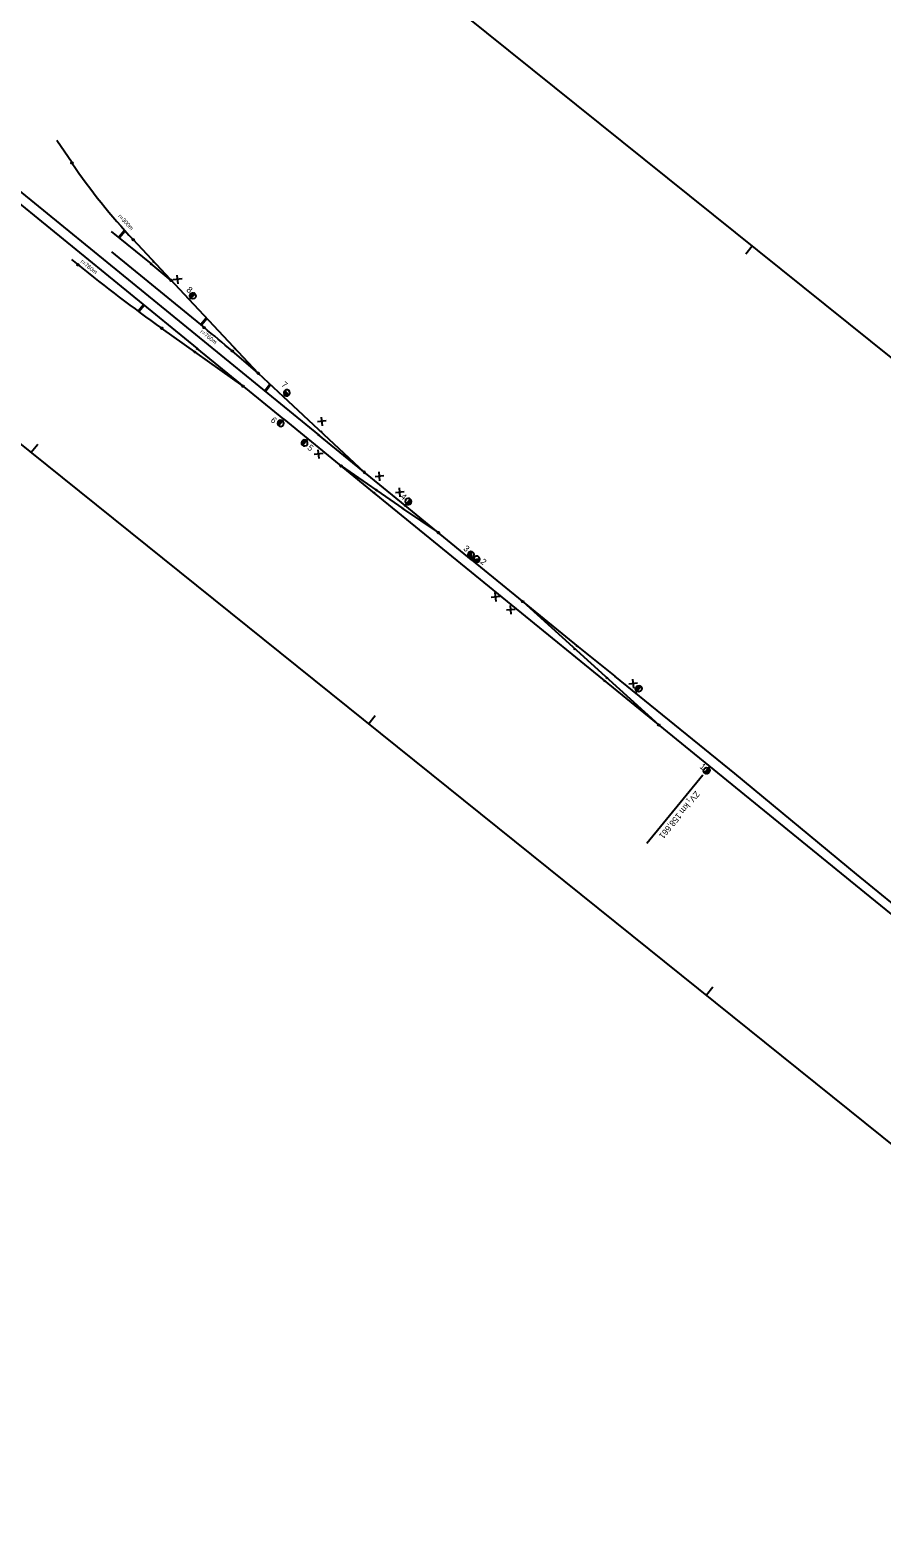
# Model space of a CAD drawing. Extents: x -486838 to -485015, y -1312876 to -1311330.
# Drawn here: x -485856 to -485443, y -1312876 to -1312145 of the extents above; entities that cross this region are included whole.
import ezdxf

# ---------------------------------------------------------------- set-up
doc = ezdxf.new("R2010")
doc.units = 0
for name, color, linetype in [('kolaj s', 7, 'Continuous'), ('Level 61', 7, 'Continuous'), ('popis 25', 7, 'Continuous'), ('popis 35', 7, 'Continuous')]:
    doc.layers.add(name, color=color, linetype=linetype)

msp = doc.modelspace()

# ---------------------------------------------------------------- linework, layer by layer
at = {"layer": 'kolaj s'}
for p, q in [((-485943.07, -1312156.89), (-485716.4, -1312341.55)), ((-485946.04, -1312160.6), (-485775.23, -1312299.76)), ((-485835.95, -1312209.75), (-485843.28, -1312198.9)), ((-485835.95, -1312209.75), (-485835.95, -1312209.75)), ((-485816.91, -1312242.92), (-485797.53, -1312258.7)), ((-485816.84, -1312252.88), (-485771.86, -1312289.52)), ((-485779.14, -1312275.89), (-485806.3, -1312246.91)), ((-485806.3, -1312246.91), (-485806.3, -1312246.91)), ((-485836.15, -1312256.51), (-485833.02, -1312259.06)), ((-485833.02, -1312259.06), (-485833.02, -1312259.06)), ((-485797.85, -1312259.09), (-485797.21, -1312258.32)), ((-485787.77, -1312266.69), (-485797.53, -1312258.7)), ((-485797.53, -1312258.7), (-485797.53, -1312258.7)), ((-485796.76, -1312257.82), (-485796.03, -1312257.14)), ((-485796.39, -1312257.48), (-485796.39, -1312257.48)), ((-485787.77, -1312266.69), (-485787.77, -1312266.69)), ((-485745.61, -1312311.68), (-485779.14, -1312275.89)), ((-485752.94, -1312317.91), (-485792.5, -1312289.87)), ((-485792.5, -1312289.87), (-485792.5, -1312289.87)), ((-485771.86, -1312289.52), (-485771.86, -1312289.52)), ((-485776.68, -1312301.7), (-485776.1, -1312300.88)), ((-485776.39, -1312301.29), (-485776.39, -1312301.29)), ((-485775.54, -1312300.14), (-485774.91, -1312299.37)), ((-485733.19, -1312334), (-485775.23, -1312299.76)), ((-485775.23, -1312299.76), (-485775.23, -1312299.76)), ((-485758.56, -1312301.27), (-485757.91, -1312300.51)), ((-485745.6, -1312311.68), (-485758.23, -1312300.89)), ((-485758.23, -1312300.89), (-485758.23, -1312300.89)), ((-485758.23, -1312300.89), (-485758.23, -1312300.89)), ((-485757.33, -1312299.9), (-485756.6, -1312299.22)), ((-485756.97, -1312299.56), (-485756.97, -1312299.56)), ((-485745.61, -1312311.68), (-485733.45, -1312323.02)), ((-485745.6, -1312311.68), (-485745.6, -1312311.68)), ((-485752.94, -1312317.91), (-485752.94, -1312317.91)), ((-485694.12, -1312359.71), (-485733.45, -1312323.02)), ((-485733.19, -1312334), (-485721.57, -1312343.47)), ((-485716.09, -1312341.16), (-485716.72, -1312341.94)), ((-485674.37, -1312375.79), (-485716.4, -1312341.55)), ((-485716.4, -1312341.55), (-485716.4, -1312341.55)), ((-485714.8, -1312339.73), (-485715.48, -1312340.47)), ((-485715.14, -1312340.1), (-485715.14, -1312340.1)), ((-485721.57, -1312343.47), (-485689.32, -1312369.74)), ((-485705.44, -1312356.61), (-485705.44, -1312356.61)), ((-485705.44, -1312356.61), (-485675.41, -1312377.18)), ((-485694.12, -1312359.71), (-485694.12, -1312359.71)), ((-485689, -1312369.36), (-485689.63, -1312370.13)), ((-485689.32, -1312369.74), (-485507.15, -1312518.16)), ((-485689.32, -1312369.74), (-485689.32, -1312369.74)), ((-485688, -1312367.95), (-485688.57, -1312368.77)), ((-485688.28, -1312368.36), (-485688.28, -1312368.36)), ((-485675.69, -1312377.59), (-485675.13, -1312376.77)), ((-485658.25, -1312388.93), (-485675.41, -1312377.18)), ((-485675.41, -1312377.18), (-485675.41, -1312377.18)), ((-485674.69, -1312376.18), (-485674.06, -1312375.41)), ((-485642.13, -1312402.07), (-485674.37, -1312375.79)), ((-485674.37, -1312375.79), (-485674.37, -1312375.79)), ((-485658.25, -1312388.93), (-485658.25, -1312388.93)), ((-485642.13, -1312402.07), (-485590.38, -1312444.22)), ((-485617.3, -1312422.29), (-485617.3, -1312422.29)), ((-485617.3, -1312422.29), (-485551.36, -1312482.14)), ((-485591.3, -1312444.11), (-485590.67, -1312443.33)), ((-485590.99, -1312443.72), (-485590.99, -1312443.72)), ((-485592.45, -1312445.55), (-485591.83, -1312444.77)), ((-485592.14, -1312445.16), (-485592.14, -1312445.16)), ((-485590.38, -1312444.22), (-485572.58, -1312458.46)), ((-485514.47, -1312505.69), (-485572.58, -1312458.46)), ((-485578, -1312461.04), (-485577.37, -1312460.26)), ((-485577.69, -1312460.65), (-485577.69, -1312460.65)), ((-485576.88, -1312459.65), (-485576.25, -1312458.87)), ((-485576.57, -1312459.26), (-485576.57, -1312459.26)), ((-485562.68, -1312466.58), (-485560.2, -1312463.51)), ((-485562.68, -1312466.58), (-485562.68, -1312466.58)), ((-485551.36, -1312482.14), (-485551.36, -1312482.14)), ((-485455.34, -1312554.41), (-485514.47, -1312505.69)), ((-485507.15, -1312518.16), (-485448.93, -1312565.48)), ((-485381.66, -1312614.83), (-485455.34, -1312554.41)), ((-485448.93, -1312565.48), (-485366.11, -1312632.98))]:
    msp.add_line(p, q, dxfattribs=at)
for points in [[(-485835.62, -1312209.53), (-485835.6, -1312209.92), (-485835.92, -1312210.15), (-485836.28, -1312209.97), (-485836.31, -1312209.57), (-485835.98, -1312209.35), (-485835.62, -1312209.53)], [(-485806.59, -1312247.18), (-485806.68, -1312246.79), (-485806.39, -1312246.52), (-485806.01, -1312246.63), (-485805.92, -1312247.02), (-485806.21, -1312247.3), (-485806.59, -1312247.18)], [(-485832.77, -1312258.75), (-485832.63, -1312259.12), (-485832.88, -1312259.43), (-485833.27, -1312259.37), (-485833.41, -1312258.99), (-485833.16, -1312258.69), (-485832.77, -1312258.75)], [(-485787.51, -1312266.38), (-485787.37, -1312266.75), (-485787.63, -1312267.06), (-485788.02, -1312267), (-485788.16, -1312266.62), (-485787.91, -1312266.31), (-485787.51, -1312266.38)], [(-485792.73, -1312290.2), (-485792.89, -1312289.84), (-485792.66, -1312289.51), (-485792.27, -1312289.55), (-485792.1, -1312289.91), (-485792.33, -1312290.24), (-485792.73, -1312290.2)], [(-485771.61, -1312289.21), (-485771.47, -1312289.58), (-485771.72, -1312289.89), (-485772.12, -1312289.83), (-485772.26, -1312289.45), (-485772.01, -1312289.15), (-485771.61, -1312289.21)], [(-485758.49, -1312301.19), (-485758.63, -1312300.82), (-485758.37, -1312300.51), (-485757.97, -1312300.58), (-485757.84, -1312300.96), (-485758.1, -1312301.27), (-485758.49, -1312301.19)], [(-485745.9, -1312311.41), (-485745.52, -1312311.3), (-485745.22, -1312311.57), (-485745.31, -1312311.96), (-485745.7, -1312312.07), (-485745.99, -1312311.8), (-485745.9, -1312311.41)], [(-485752.71, -1312317.58), (-485752.54, -1312317.95), (-485752.78, -1312318.27), (-485753.17, -1312318.24), (-485753.34, -1312317.87), (-485753.11, -1312317.55), (-485752.71, -1312317.58)], [(-485705.13, -1312356.86), (-485705.51, -1312357), (-485705.81, -1312356.75), (-485705.75, -1312356.36), (-485705.38, -1312356.22), (-485705.07, -1312356.47), (-485705.13, -1312356.86)], [(-485694.39, -1312360), (-485694, -1312360.09), (-485693.73, -1312359.8), (-485693.85, -1312359.41), (-485694.24, -1312359.33), (-485694.51, -1312359.62), (-485694.39, -1312360)], [(-485658.56, -1312388.68), (-485658.19, -1312388.54), (-485657.88, -1312388.79), (-485657.94, -1312389.18), (-485658.32, -1312389.32), (-485658.62, -1312389.07), (-485658.56, -1312388.68)], [(-485617.05, -1312421.98), (-485616.9, -1312422.35), (-485617.15, -1312422.66), (-485617.55, -1312422.6), (-485617.69, -1312422.23), (-485617.44, -1312421.92), (-485617.05, -1312421.98)], [(-485560.51, -1312463.26), (-485559.88, -1312463.76), (-485559.62, -1312464.51), (-485559.74, -1312465.25), (-485560.23, -1312465.85), (-485560.95, -1312466.13), (-485561.71, -1312466.01), (-485562.33, -1312465.51), (-485562.6, -1312464.79), (-485562.48, -1312464.03), (-485561.98, -1312463.41), (-485561.26, -1312463.14), (-485560.51, -1312463.26), (-485560.86, -1312463.29), (-485560.47, -1312463.61), (-485560.66, -1312463.84), (-485561.32, -1312463.3), (-485561.66, -1312463.41), (-485560.85, -1312464.07), (-485561.04, -1312464.31), (-485561.93, -1312463.58), (-485562.12, -1312463.81), (-485561.23, -1312464.54), (-485561.41, -1312464.78), (-485562.3, -1312464.05), (-485562.38, -1312464.37), (-485561.6, -1312465.01), (-485561.79, -1312465.24), (-485562.45, -1312464.7), (-485562.37, -1312465.16), (-485561.98, -1312465.47)], [(-485551.11, -1312481.83), (-485550.97, -1312482.2), (-485551.21, -1312482.51), (-485551.61, -1312482.45), (-485551.75, -1312482.07), (-485551.5, -1312481.76), (-485551.11, -1312481.83)]]:
    msp.add_lwpolyline(points, dxfattribs=at)
for centre, radius, start, end in [((-485587.38, -1312041.78), 300, 214.04753, 223.13629), ((-485353.01, -1311669.83), 760, 230.83205, 234.67055), ((-486251.86, -1312878.76), 760, 49.49538, 50.83347)]:
    msp.add_arc(centre, radius, start, end, dxfattribs=at)
at = {"layer": 'Level 61'}
for p, q in [((-486160.87, -1311724.08), (-485014.82, -1312644.65)), ((-485200.81, -1312876.2), (-486346.87, -1311955.63)), ((-485505.98, -1312250.12), (-485509.11, -1312254.02)), ((-485852.57, -1312346.26), (-485855.7, -1312350.16)), ((-485688.85, -1312477.77), (-485691.98, -1312481.67)), ((-485525.12, -1312609.28), (-485528.25, -1312613.18))]:
    msp.add_line(p, q, dxfattribs=at)
at = {"layer": 'popis 25'}
for p, q in [((-485813.02, -1312245.41), (-485810.84, -1312242.67)), ((-485812.67, -1312245.69), (-485810.49, -1312242.96)), ((-485803.69, -1312281.23), (-485801.51, -1312278.49)), ((-485803.33, -1312281.51), (-485801.15, -1312278.78)), ((-485773.27, -1312287.78), (-485771.09, -1312285.04)), ((-485772.91, -1312288.06), (-485770.73, -1312285.32)), ((-485742.3, -1312319.92), (-485740.12, -1312317.18)), ((-485741.95, -1312320.2), (-485739.76, -1312317.47))]:
    msp.add_line(p, q, dxfattribs=at)
at = {"layer": 'popis 35'}
for p, q in [((-485782.57, -1312265.97), (-485786.82, -1312266.44)), ((-485784.47, -1312268.33), (-485784.93, -1312264.08)), ((-485779.14, -1312275.89), (-485776.27, -1312273.18)), ((-485779.14, -1312275.89), (-485779.14, -1312275.89)), ((-485732.77, -1312322.28), (-485733.45, -1312323.02)), ((-485732.84, -1312320.16), (-485733.22, -1312320.84)), ((-485733.22, -1312320.84), (-485733.2, -1312321.57)), ((-485732.77, -1312322.28), (-485733.21, -1312321.58)), ((-485733.2, -1312321.57), (-485732.77, -1312322.28)), ((-485732.55, -1312320.73), (-485733.02, -1312321.23)), ((-485733.02, -1312321.23), (-485732.93, -1312321.58)), ((-485732.93, -1312321.58), (-485732.22, -1312320.81)), ((-485732.22, -1312319.75), (-485732.84, -1312320.16)), ((-485731.93, -1312320.95), (-485732.78, -1312321.86)), ((-485732.78, -1312321.86), (-485732.77, -1312322.28)), ((-485732.77, -1312322.28), (-485731.69, -1312321.13)), ((-485732.77, -1312322.28), (-485731.69, -1312321.13)), ((-485732.35, -1312322.27), (-485732.77, -1312322.28)), ((-485732.77, -1312322.28), (-485732.04, -1312322.67)), ((-485731.49, -1312321.35), (-485732.35, -1312322.27)), ((-485731.47, -1312319.7), (-485732.22, -1312319.75)), ((-485732.06, -1312322.4), (-485731.34, -1312321.63)), ((-485731.7, -1312322.46), (-485732.06, -1312322.4)), ((-485732.04, -1312322.67), (-485731.32, -1312322.61)), ((-485731.24, -1312321.96), (-485731.7, -1312322.46)), ((-485730.72, -1312320.09), (-485731.47, -1312319.7)), ((-485731.32, -1312322.61), (-485730.65, -1312322.21)), ((-485730.3, -1312320.81), (-485730.72, -1312320.09)), ((-485730.65, -1312322.21), (-485730.32, -1312321.56)), ((-485730.32, -1312321.56), (-485730.3, -1312320.81)), ((-485733.19, -1312334), (-485735.67, -1312337.08)), ((-485733.19, -1312334), (-485733.19, -1312334)), ((-485714.52, -1312337.15), (-485714.99, -1312332.9)), ((-485712.63, -1312334.79), (-485716.88, -1312335.26)), ((-485721.57, -1312343.47), (-485724.04, -1312346.55)), ((-485721.57, -1312343.47), (-485721.57, -1312343.47)), ((-485716.08, -1312353), (-485716.54, -1312348.75)), ((-485714.18, -1312350.65), (-485718.43, -1312351.11)), ((-485684.67, -1312361.42), (-485688.92, -1312361.88)), ((-485686.56, -1312363.77), (-485687.03, -1312359.52)), ((-485674.81, -1312369.19), (-485679.06, -1312369.65)), ((-485676.71, -1312371.54), (-485677.17, -1312367.29)), ((-485674.37, -1312375.79), (-485671.9, -1312372.72)), ((-485674.37, -1312375.79), (-485674.37, -1312375.79)), ((-485642.13, -1312402.07), (-485642.13, -1312402.07)), ((-485628.34, -1312419.9), (-485632.59, -1312420.36)), ((-485630.23, -1312422.26), (-485630.7, -1312418.01)), ((-485620.96, -1312426.12), (-485625.21, -1312426.59)), ((-485622.86, -1312428.48), (-485623.32, -1312424.23)), ((-485561.61, -1312461.91), (-485565.86, -1312462.37)), ((-485563.5, -1312464.26), (-485563.96, -1312460.01)), ((-485526.53, -1312502.37), (-485529, -1312505.45)), ((-485526.53, -1312502.37), (-485526.53, -1312502.37)), ((-485529.92, -1312506.5), (-485557.1, -1312539.62))]:
    msp.add_line(p, q, dxfattribs=at)
for points in [[(-485776.54, -1312272.89), (-485775.99, -1312273.47), (-485775.83, -1312274.25), (-485776.05, -1312274.97), (-485776.61, -1312275.5), (-485777.37, -1312275.68), (-485778.11, -1312275.46), (-485778.65, -1312274.88), (-485778.82, -1312274.13), (-485778.61, -1312273.39), (-485778.02, -1312272.85), (-485777.28, -1312272.68), (-485776.54, -1312272.89), (-485776.89, -1312272.88), (-485776.55, -1312273.25), (-485776.77, -1312273.45), (-485777.35, -1312272.83), (-485777.71, -1312272.89), (-485776.99, -1312273.66), (-485777.21, -1312273.86), (-485778, -1312273.02), (-485778.21, -1312273.23), (-485777.43, -1312274.07), (-485777.64, -1312274.27), (-485778.43, -1312273.43), (-485778.55, -1312273.75), (-485777.86, -1312274.48), (-485778.08, -1312274.68), (-485778.66, -1312274.06), (-485778.64, -1312274.52), (-485778.3, -1312274.89)], [(-485735.98, -1312336.83), (-485735.36, -1312337.33), (-485734.6, -1312337.44), (-485733.88, -1312337.17), (-485733.38, -1312336.54), (-485733.27, -1312335.79), (-485733.57, -1312335.04), (-485734.16, -1312334.58), (-485734.92, -1312334.46), (-485735.64, -1312334.73), (-485736.14, -1312335.35), (-485736.25, -1312336.11), (-485735.98, -1312336.83), (-485736.02, -1312336.48), (-485735.63, -1312336.79), (-485735.44, -1312336.56), (-485736.1, -1312336.02), (-485736.07, -1312335.66), (-485735.25, -1312336.32), (-485735.07, -1312336.09), (-485735.96, -1312335.37), (-485735.77, -1312335.13), (-485734.88, -1312335.85), (-485734.69, -1312335.62), (-485735.59, -1312334.9), (-485735.28, -1312334.76), (-485734.5, -1312335.39), (-485734.31, -1312335.15), (-485734.98, -1312334.62), (-485734.48, -1312334.64), (-485734.13, -1312334.92)], [(-485724.35, -1312346.3), (-485723.73, -1312346.8), (-485722.97, -1312346.91), (-485722.25, -1312346.64), (-485721.75, -1312346.02), (-485721.64, -1312345.26), (-485721.94, -1312344.52), (-485722.53, -1312344.05), (-485723.29, -1312343.93), (-485724.01, -1312344.2), (-485724.51, -1312344.83), (-485724.62, -1312345.59), (-485724.35, -1312346.3), (-485724.39, -1312345.95), (-485724, -1312346.26), (-485723.81, -1312346.03), (-485724.48, -1312345.5), (-485724.44, -1312345.14), (-485723.62, -1312345.8), (-485723.44, -1312345.56), (-485724.33, -1312344.84), (-485724.15, -1312344.61), (-485723.25, -1312345.33), (-485723.06, -1312345.09), (-485723.96, -1312344.37), (-485723.65, -1312344.23), (-485722.87, -1312344.86), (-485722.69, -1312344.63), (-485723.35, -1312344.09), (-485722.85, -1312344.11), (-485722.5, -1312344.39)], [(-485671.59, -1312372.97), (-485672.21, -1312372.46), (-485672.97, -1312372.35), (-485673.69, -1312372.63), (-485674.19, -1312373.25), (-485674.3, -1312374.01), (-485674.03, -1312374.73), (-485673.4, -1312375.23), (-485672.64, -1312375.34), (-485671.93, -1312375.07), (-485671.43, -1312374.44), (-485671.31, -1312373.68), (-485671.59, -1312372.97), (-485671.55, -1312373.32), (-485671.94, -1312373), (-485672.13, -1312373.24), (-485671.46, -1312373.77), (-485671.53, -1312374.1), (-485672.31, -1312373.47), (-485672.5, -1312373.71), (-485671.61, -1312374.43), (-485671.79, -1312374.66), (-485672.69, -1312373.94), (-485672.88, -1312374.17), (-485671.98, -1312374.89), (-485672.29, -1312375.03), (-485673.07, -1312374.41), (-485673.25, -1312374.64), (-485672.59, -1312375.17), (-485673.09, -1312375.16), (-485673.44, -1312374.88)], [(-485642.23, -1312401.1), (-485641.51, -1312400.82), (-485641.02, -1312400.21), (-485640.9, -1312399.44), (-485641.18, -1312398.72), (-485641.79, -1312398.23), (-485642.56, -1312398.11), (-485643.28, -1312398.4), (-485643.77, -1312399), (-485643.89, -1312399.77), (-485643.61, -1312400.49), (-485643, -1312400.98), (-485642.23, -1312401.1), (-485642.41, -1312400.75), (-485643.05, -1312400.81), (-485643.36, -1312400.56), (-485642.51, -1312400.47), (-485642.51, -1312400.15), (-485643.53, -1312400.3), (-485643.67, -1312399.99), (-485642.54, -1312399.87), (-485642.57, -1312399.59), (-485643.74, -1312399.68), (-485643.7, -1312399.39), (-485642.57, -1312399.27), (-485642.6, -1312398.99), (-485643.59, -1312399.1), (-485643.38, -1312398.75), (-485642.67, -1312398.68), (-485642.67, -1312398.36), (-485643.02, -1312398.39)], [(-485642.56, -1312398.13), (-485642.13, -1312402.07), (-485638.19, -1312401.64)], [(-485638.17, -1312401.63), (-485638.46, -1312400.91), (-485639.06, -1312400.42), (-485639.87, -1312400.31), (-485640.55, -1312400.59), (-485641.04, -1312401.19), (-485641.16, -1312401.96), (-485640.88, -1312402.68), (-485640.27, -1312403.17), (-485639.55, -1312403.29), (-485638.78, -1312403.01), (-485638.29, -1312402.4), (-485638.17, -1312401.63), (-485638.49, -1312401.85), (-485638.43, -1312402.34), (-485638.71, -1312402.69), (-485638.8, -1312401.92), (-485639.08, -1312401.95), (-485638.97, -1312402.93), (-485639.28, -1312403.07), (-485639.4, -1312401.95), (-485639.71, -1312402.02), (-485639.56, -1312403.1), (-485639.88, -1312403.1), (-485639.99, -1312402.05), (-485640.28, -1312402.08), (-485640.17, -1312403.06), (-485640.52, -1312402.78), (-485640.6, -1312402.08), (-485640.88, -1312402.11), (-485640.83, -1312402.53)], [(-485528.69, -1312505.7), (-485529.32, -1312505.19), (-485529.59, -1312504.48), (-485529.48, -1312503.72), (-485528.98, -1312503.09), (-485528.26, -1312502.82), (-485527.47, -1312502.95), (-485526.89, -1312503.43), (-485526.6, -1312504.15), (-485526.71, -1312504.91), (-485527.22, -1312505.53), (-485527.93, -1312505.81), (-485528.69, -1312505.7), (-485528.34, -1312505.66), (-485528.73, -1312505.34), (-485528.54, -1312505.11), (-485527.88, -1312505.64), (-485527.54, -1312505.53), (-485528.35, -1312504.88), (-485528.17, -1312504.64), (-485527.27, -1312505.36), (-485527.08, -1312505.13), (-485527.98, -1312504.41), (-485527.79, -1312504.17), (-485526.89, -1312504.89), (-485526.82, -1312504.57), (-485527.6, -1312503.94), (-485527.41, -1312503.71), (-485526.75, -1312504.24), (-485526.88, -1312503.75), (-485527.23, -1312503.47)]]:
    msp.add_lwpolyline(points, dxfattribs=at)
msp.add_arc((-485732.71, -1312322.22), 1.5, 345.23439, 108.77924, dxfattribs=at)

# ---------------------------------------------------------------- texts
at = {"layer": 'popis 25'}
for s, rotation, p in [('r=300m', 313.22682, (-485813.78, -1312235.69)), ('r=760m', 321.22682, (-485832.04, -1312257.87)), ('r=760m', 321.22682, (-485773.97, -1312291.86))]:
    msp.add_text(s, height=2, rotation=rotation, dxfattribs=at).set_placement(p)
at = {"layer": 'popis 35'}
for s, height, rotation, p in [('8', 3, 320.62682, (-485780.74, -1312271.7)), ('7', 3, 320.62682, (-485734.66, -1312317.68)), ('6', 3, 320.62682, (-485739.86, -1312334.9)), ('5', 3, 320.62682, (-485722.08, -1312348.26)), ('4', 3, 320.62682, (-485676.84, -1312371.95)), ('3', 3, 320.62682, (-485646.39, -1312397.1)), ('2', 3, 320.62682, (-485638.15, -1312403.49)), ('1', 3, 320.62682, (-485531.75, -1312502.76)), ('ZV  km 158,661', 3, 230.62682, (-485533.49, -1312513.91)), ('1', 2, 230.62682, (-485537.41, -1312517.37))]:
    msp.add_text(s, height=height, rotation=rotation, dxfattribs=at).set_placement(p)

doc.saveas('drawing.dxf')
